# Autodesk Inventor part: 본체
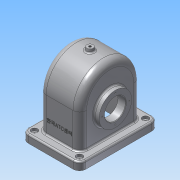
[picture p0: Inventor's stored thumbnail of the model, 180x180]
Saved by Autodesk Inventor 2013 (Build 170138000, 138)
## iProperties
Created: 2016-10
Part Number: 본체
Material: 알루미늄 6061
Document SubType Name: Modeling
Designer: Administrator
Mass: 1165.23 g
Surface Area: 1199.61 cm^2
Volume: 429.976 cm^3
Density: 2.71 g/cm^3
Author: Administrator
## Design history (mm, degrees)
sketch "스케치1"
  geometry: L1 (-43, 75)-(43, 75); L2 (55, 63)-(55, -63); L3 (43, -75)-(-43, -75); L4 (-55, -63)-(-55, 63); A1 r 12 centre (-43, 63) between (-43, 75) and (-55, 63); A2 r 12 centre (43, 63) between (55, 63) and (43, 75); A3 r 12 centre (43, -63) between (43, -75) and (55, -63); A4 r 12 centre (-43, -63) between (-55, -63) and (-43, -75); 3 further points
  constraints: 8 end point, 8 point on circle, 8 tangent, 4 centre point, 3 equal radius, 2 midpoint, 2 parallel, 1 horizontal, 1 horizontal alignment, 1 perpendicular, 1 vertical alignment
  dimensions: "d0" = 12 radius of A1; "d1" = 110 distance between parallel lines of L2 L4; "d2" = 150 distance between parallel lines of L3 L1
extrude "돌출1" new body sketch "스케치1" distance "d3" = 15; taper "d4" = 0 deg
sketch "스케치2"
  geometry: L1 (63, 0)-(-63, 0) reference; L2 (-63, 0)-(-75, 0) reference; L3 (75, 0)-(63, 0) reference; L4 (-58, 0)-(-58, 80); L5 (58, 80)-(58, 0); A1 r 58 centre (0, 80) between (58, 80) and (-58, 80); 2 further points
  constraints: 4 end point, 2 perpendicular, 2 point on circle, 2 point on line, 1 centre point, 1 midpoint, 1 parallel, 1 tangent, 1 vertical alignment
  dimensions: "d5" = 58 radius of A1; "d7" = 80 distance of point (0, 0) A1.centre
extrude "돌출2" join sketch "스케치2" stored distance "d8" = 77; taper "d9" = 0 deg
node "작업 평면1"
sketch "스케치4"
  geometry: C1 r 6 at (0, 0); 1 further point
  constraints: 1 centre point, 1 coincident
  dimensions: "d15" = 12 diameter of C1
extrude "돌출4" join sketch "스케치4" distance "d17" = 40; taper "d18" = 10 deg
sketch "스케치5"
  geometry: C1 r 31 at (-65, 0); 1 further point
  constraints: 1 centre point, 1 horizontal alignment
  dimensions: "d19" = 65 distance of point (0, 0) C1.centre; "d20" = 62 diameter of C1
extrude "돌출5" join sketch "스케치5" distance "d21" = 10; taper "d22" = 0 deg
sketch "스케치6"
  geometry: C1 r 37.5 at (65, 0); 1 further point
  constraints: 1 centre point, 1 horizontal alignment
  dimensions: "d23" = 65 distance of point (0, 0) C1.centre; "d24" = 75 diameter of C1
extrude "돌출6" join sketch "스케치6" distance "d25" = 5; taper "d26" = 0 deg
sketch "스케치7"
  geometry: L1 (-58, 15)-(-58, 80) reference; L2 (58, 80)-(58, 15) reference; L3 (-52, 0)-(-52, 80); L4 (52, 80)-(52, 0); L5 (63, 0)-(-63, 0) reference; A1 r 58 centre (0, 80) between (58, 80) and (-58, 80) reference; A2 r 52 centre (0, 80) between (52, 80) and (-52, 80); 1 further point
  constraints: 4 end point, 2 point on circle, 2 point on line, 1 centre point
  dimensions: "d27" = 6 distance between parallel lines of L2 L4; "d28" = 6 radial gap between concentric circles of A1 A2; "d29" = 6 distance between parallel lines of L1 L3
extrude "돌출7" cut sketch "스케치7" stored distance "d30" = 67; taper "d31" = 0 deg
sketch "스케치8"
  geometry: L1 (43.5, 27.5)-(43.5, 102.5) reference; L2 (43.5, 65)-(19.5, 65); L3 (19.5, 65)-(19.5, 93); L4 (33.5, 80)-(33.5, 132) reference; L5 (33.5, 0)-(33.5, 80) reference; L6 (19.5, 93)-(33.5, 104.747); L7 (33.5, 104.747)-(33.5, 65); L8 (19.5, 65)-(33.5, 65); 1 further point
  constraints: 10 end point, 3 point on line, 2 perpendicular, 1 collinear, 1 midpoint
  dimensions: "d32" = 24 distance of L2.start L2.end; "d33" = 50 deg angle of L6 L3; "d35" = 56 diameter of L3.end L2
revolve "회전1" sketch "스케치8" stored, may be unused: angle "d36" = 90 deg
hole "구멍1" diameter "d39" = 40; stored, may be unused: countersink angle "d43" = 90 deg, drill point angle "d45" = 118 deg; dims "d37" = 10, "d38" = 10, "d40" = 6, "d41" = 4, "d42" = 2, "d44" = 8
hole "구멍2" diameter "d48" = 4.459; stored, may be unused: countersink angle "d52" = 90 deg, drill point angle "d54" = 118 deg; dims "d46" = 10, "d47" = 10, "d49" = 28, "d50" = 4, "d51" = 2, "d53" = 30
hole "구멍3" diameter "d57" = 5; stored, may be unused: countersink angle "d61" = 90 deg, drill point angle "d63" = 118 deg; dims "d55" = 10, "d56" = 10, "d58" = 28, "d59" = 12, "d60" = 5, "d62" = 30
hole "구멍4" diameter "d66" = 5; stored, may be unused: countersink angle "d70" = 90 deg, drill point angle "d72" = 118 deg; dims "d64" = 10, "d65" = 10, "d67" = 28, "d68" = 12, "d69" = 5, "d71" = 30
hole "구멍5" diameter "d75" = 5; stored, may be unused: countersink angle "d79" = 90 deg, drill point angle "d81" = 118 deg; dims "d73" = 10, "d74" = 10, "d76" = 28, "d77" = 12, "d78" = 5, "d80" = 30
hole "구멍6" diameter "d84" = 5; stored, may be unused: countersink angle "d88" = 90 deg, drill point angle "d90" = 118 deg; dims "d82" = 10, "d83" = 10, "d85" = 28, "d86" = 12, "d87" = 5, "d89" = 30
chamfer "모따기1" distance "d91" = 1; stored, may be unused: second distance "d92" = 2, angle "d93" = 45 deg
fillet "모깎기1" dims "d94" = 8
fillet "모깎기2" dims "d95" = 13
fillet "모깎기3" dims "d96" = 3
fillet "모깎기4" dims "d97" = 3
fillet "모깎기5" dims "d98" = 3
sketch "스케치9"
  geometry: C1 r 31 at (0, 0) reference; 2 further points
  constraints: 1 horizontal alignment
  dimensions: "d99" = 26 distance of point (-26, 0) C1.centre
hole "구멍7" sketch "스케치9" at (-26, 0) diameter "d100" = 2.459; stored, may be unused: countersink angle "d104" = 90 deg, drill point angle "d106" = 118 deg; dims "d101" = 6, "d102" = 12, "d103" = 5, "d105" = 8
sketch "스케치10"
  geometry: C1 r 37.5 at (0, 0) reference; 2 further points
  constraints: 1 horizontal alignment
  dimensions: "d110" = 29 distance of point (29, 0) C1.centre
hole "구멍8" sketch "스케치10" at (29, 0) diameter "d111" = 2.459; stored, may be unused: countersink angle "d115" = 90 deg, drill point angle "d117" = 118 deg; dims "d112" = 6, "d113" = 12, "d114" = 5, "d116" = 8
sketch "스케치11"
  geometry: L1 (-17.5, -80)-(68.5, -80) reference; 3 further points
  constraints: 1 midpoint, 1 vertical alignment, 1 other
  dimensions: "d121" = 40 distance from line of L1 point (25.5, -40)
feature "엠보싱1" sketch "스케치11" dims "d0" = 12, "d1" = 110, "d2" = 150, "d5" = 58, "d7" = 80, "d122" = 0.5, "d123" = 0
node "솔리드1"
pattern_circular "원형 패턴1" dims angle "d108" = 360 deg
pattern_circular "원형 패턴2" dims angle "d119" = 360 deg
other parameters: "d14" = 144
